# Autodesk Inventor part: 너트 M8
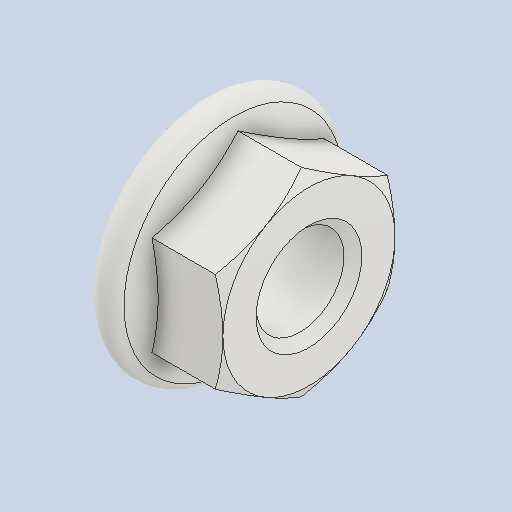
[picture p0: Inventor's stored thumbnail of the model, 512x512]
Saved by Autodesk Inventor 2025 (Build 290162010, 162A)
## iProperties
Created: 2024-07
Part Number: 너트 M8
Material: 스테인리스강
Description: 플랜지붙이 6각 너트 - 일반 스레드
Document SubType Name: Modeling
Designer: 학생
Density: 8 g/cm^3
Appearance: 기본값
Author: jhkim
Sending System: Autodesk Inventor 2025
Preprocessor: ST-DEVELOPER v20
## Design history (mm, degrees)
feature "Solid1"
node "솔리드1"
